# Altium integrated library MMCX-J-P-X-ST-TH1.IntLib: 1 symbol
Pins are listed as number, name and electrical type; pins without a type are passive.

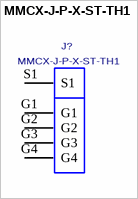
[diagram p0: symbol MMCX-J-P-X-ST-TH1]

## MMCX-J-P-X-ST-TH1
designator J?
MMCX STRAIGHT, THROUGH HOLE JACK-50 OHM.; MANUFACTURER: SAMTEC
footprint MMCX-J-P-X-ST-TH1
pins: G1, G2, G3, G4, S1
